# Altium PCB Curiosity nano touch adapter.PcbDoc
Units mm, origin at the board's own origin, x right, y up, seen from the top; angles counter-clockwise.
Board outline 60 x 100 mm, 2 copper layers (Top Layer, Bottom Layer); 22 components, 57 nets, 293 pads, 14 vias.
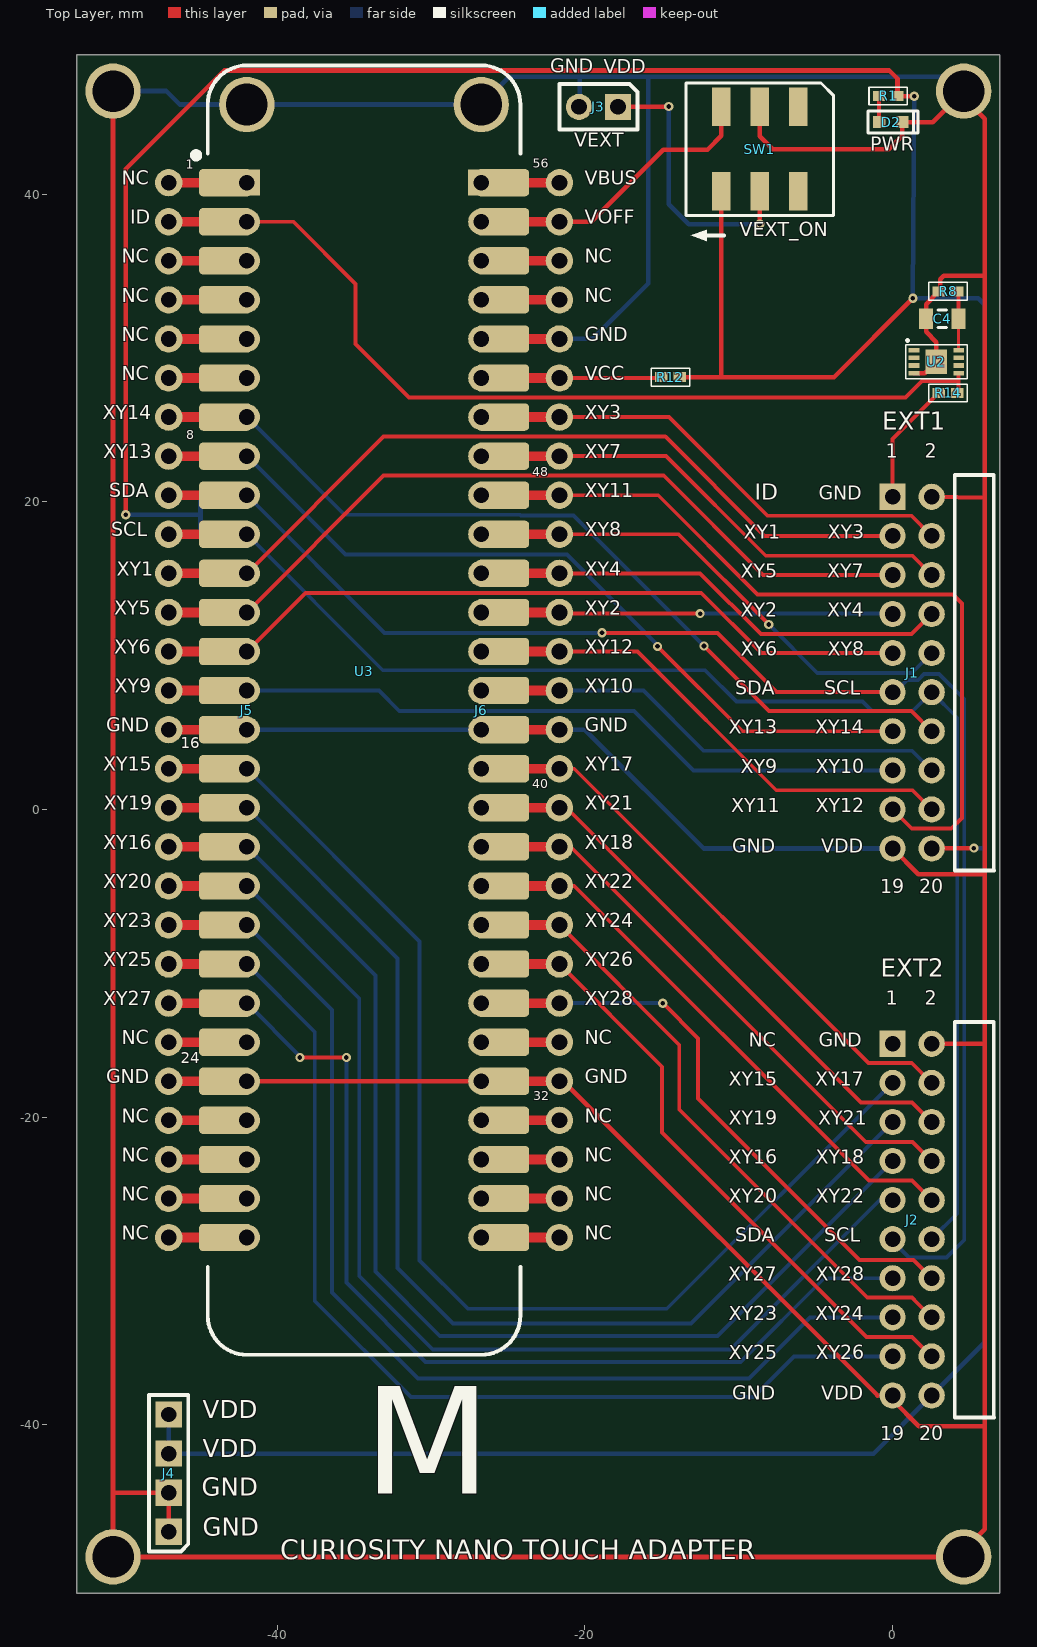
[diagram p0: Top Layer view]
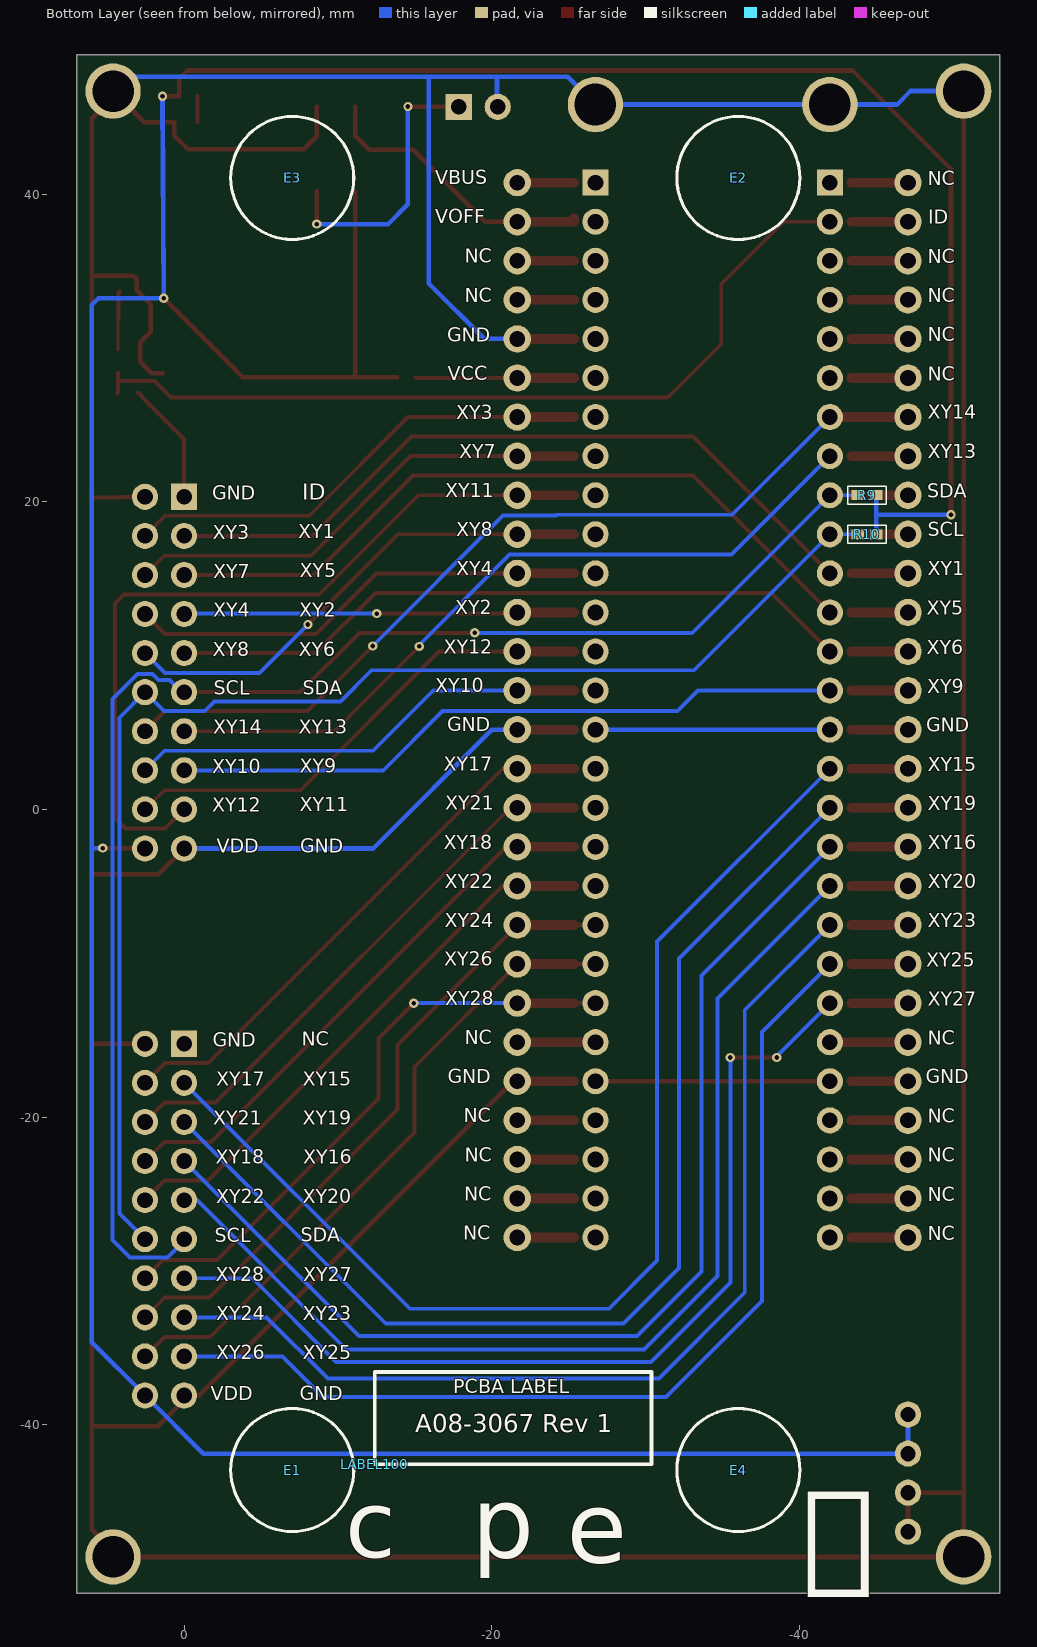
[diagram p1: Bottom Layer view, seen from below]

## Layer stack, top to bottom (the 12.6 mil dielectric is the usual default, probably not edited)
Top Solder: solder mask 0.0102, Solder Resist, Dk 3.5
Top Layer: signal copper 0.0356
Dielectric 1: dielectric 0.32, FR-4, Dk 4.8
Bottom Layer: signal copper 0.0356
Bottom Solder: solder mask 0.0102, Solder Resist, Dk 3.5

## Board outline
-53.03,-50.95 6.97,-50.95 6.97,49.05 -53.03,49.05

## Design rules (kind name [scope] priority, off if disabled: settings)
Clearance [All] p1: gap=0.2 ignorepadtopadclearanceinfootprint=FALSE except(0: Arc-Hole Track-Hole SMDPad-Hole THPad-Hole Via-Hole Fill-Hole Poly-Hole Region-Hole Text-Hole)
HoleSize [All] p1: absolutevalues=TRUE maxlimit=10 minlimit=0.025 maxpercent=80.000 minpercent=20.000
MinimumSolderMaskSliver [All] p1: minsoldermaskwidth=0.1
PolygonConnect [All] p1: connectstyle=Relief reliefconductorwidth=0.254 reliefentries=4 polygonreliefangle="90 Angle" airgapwidth=0.254
RoutingVias [All] p1: holewidth=0.3 width=0.6 viastyle="Through Hole" minholewidth=0.3 minwidth=0.6 maxholewidth=0.3 maxwidth=0.6
SilkToSilkClearance [All] p1: silktosilkclearance=0.1
SilkToSolderMaskClearance [IsPad] p1: minsilkscreentomaskgap=0.1 clearancetoexposedcopper=TRUE
SolderMaskExpansion [All] p1: expansion=0.102
Width [All] p1: maxlimit=10 minlimit=0.2 preferedwidth=0.2
26 further rules are at their usual default settings.

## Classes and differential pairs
component class "Curiosity nano touch adapter_TopLevel": E1 E2 E3 E4 LABEL100 PCB1 PCBADOC1 PCBADOC2 TEST1
component class "Curiosity nano touch adapter": C4 D2 J1 J2 J3 J4 J5 J6 R1 R8 R9 R10 R12 R14 SW1 U2 U3

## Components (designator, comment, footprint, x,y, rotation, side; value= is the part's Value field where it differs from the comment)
C4 "Generic part, no manufacturer specified." AP1-00069 3.226,31.902 r180 top value=4.7uF
D2 "Farnell no. 1652078" AP4-00017 -0.122,44.681 r180 top value=SML-310MTT86N
E1 "RUBBER FEET" AP8-00192 -7.03,-42.95 r180 bottom value=SJ-5076
E2 "RUBBER FEET" AP8-00192 -36.03,41.05 r180 bottom value=SJ-5076
E3 "RUBBER FEET" AP8-00192 -7.03,41.05 r180 bottom value=SJ-5076
E4 "RUBBER FEET" AP8-00192 -36.03,-42.95 r180 bottom value=SJ-5076
J1 "" AP8-01078 1.27,8.89 r270 top value=1125-1210S0R138R1
J2 "" AP8-01078 1.27,-26.67 r270 top value=1125-1210S0R138R1
J3 "HEADER 1x2" AP8-01074 -19.121,45.672 r180 top value=1125-1102S0S113R1
J4 "None" AP8-00176 -47.061,-43.152 r90 top value=HMTSW-104-23-F-S-237
J5 "Not suitable for pick-and-place (missing tab)" AP8-01174#1 -41.981,6.454 r270 top value=2185-128SS0CUNT1
J6 "Not suitable for pick-and-place (missing tab)" AP8-01174#2 -26.741,6.454 r270 top value=2185-128SS0CUNT1
LABEL100 "" AP8-00317 -12.395,-42.57 r180 bottom value="Label PCBA"
R1 "" AP2-00000 -0.284,46.383 r180 top value=470R
R8 "" AP2-00000 3.607,33.68 r180 top value=100k
R9 "" AP2-00000 -44.394,20.424 r0 bottom value=10k
R10 "" AP2-00000 -44.394,17.884 r0 bottom value=10k
R12 "" AP2-00000 -14.447,28.095 r0 top value=0R
R14 "" AP2-00000 3.607,27.076 r180 top value=0R
SW1 "" AP8-00684 -8.631,42.922 r180 top value=JS202011SCQN
U2 "" AP6-00409 2.845,29.108 r0 top value="ATSHA204A SWI UDFN8"
U3 "" AP8-01154 -34.361,6.454 r0 top value=CNANO56_HOST_CONN

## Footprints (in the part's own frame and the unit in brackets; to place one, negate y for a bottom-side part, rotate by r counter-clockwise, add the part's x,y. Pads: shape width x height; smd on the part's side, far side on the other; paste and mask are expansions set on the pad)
AP1-00069 [mm] "0805 Cap"
  rect 0.9x1.35 smd: 1(-1.05,0) 2(1.05,0)
  silkscreen extent -0.28,-0.57 0.28,0.57, body extent -1,-0.63 1,0.63, height 0.78
AP2-00000 [mm] "Standard 0402 SMD resistor footprint"
  rect 0.8x0.65 smd: 1(-0.6,0) 2(0.6,0)
  silkscreen extent -1.25,-0.58 1.25,0.58, body extent -0.5,-0.3 0.5,0.3, height 0.2
AP4-00017 [mm]
  rect 0.8x0.8 smd: 1(-0.75,0) 2(0.75,0)
  silkscreen extent -1.76,-0.72 1.47,0.72, body extent -0.83,-0.36 0.81,0.37, height 0.68
AP6-00409 [mm]
  rect 0.7x0.3 smd mask-1: 1(-1.45,0.75) 2(-1.45,0.25) 3(-1.45,-0.25) 4(-1.45,-0.75) 5(1.45,-0.75) 6(1.45,-0.25) 7(1.45,0.25) 8(1.45,0.75)
  rect 1.4x1.6 smd paste-0.025 mask+0.075: 9(0,0)
  silkscreen extent -2,-1.1 2,1.45, body extent -1.55,-1.05 1.55,1.05, height 0.6
AP8-00176 [mm]
  rect 1.7x1.7 / inner round 1.7 / far side round 1.7 hole 1: 1(-3.81,0) 2(-1.27,0) 3(1.27,0) 4(3.81,0)
  silkscreen extent -5.08,-1.27 5.08,1.27, body extent -5.08,-1.24 5.08,1.24, height 8.56
AP8-00192 [mm]
  silkscreen extent -4,-4 4,4, body extent -4,-4 4,4, height 2.79
AP8-00317 [mm] "Placement area for 18x6mm sticker"
  silkscreen extent 0,0 18,6
AP8-00684 [mm] "Slide Switch, C&K, 2 Pos 2 Pol"
  rect 1.2x2.5 smd: 1(-2.5,-2.75) 2(0,-2.75) 3(2.5,-2.75) 4(-2.5,2.75) 5(0,2.75) 6(2.5,2.75)
  silkscreen extent -4.8,-4.3 4.8,4.3, body extent -4.52,-3.8 4.55,3.8, height 5.5
AP8-01074 [mm] "Pin header 1 x 2,  2.54mm, THM, PIP, with Pick plate"
  rect 2.1x2.1 on Top Paste: 0(-1.27,0) 0(1.27,0)
  rect 1.7x1.7 / inner round 1.7 / far side rect 1.7x1.7 hole 1.02: 1(-1.27,0)
  round 1.7 hole 1.02: 2(1.27,0)
  silkscreen extent -2.54,-1.48 2.54,1.48, body extent -2.54,-1.27 2.54,1.27, height 8.38
AP8-01078 [mm] "2x10 Right angle 2.54mm THM, Pick plate"
  rect 1.7x1.7 / inner round 1.7 / far side rect 1.7x1.7 hole 1.02: 1(-11.43,-1.27)
  rect 2.1x2.1 on Top Paste: 1(-11.43,-1.27) 2(-11.43,1.27) 3(-8.89,-1.27) 4(-8.89,1.27) 5(-6.35,-1.27) 6(-6.35,1.27) 7(-3.81,-1.27) 8(-3.81,1.27) 9(-1.27,-1.27) 10(-1.27,1.27) 11(1.27,-1.27) 12(1.27,1.27) 13(3.81,-1.27) 14(3.81,1.27) 15(6.35,-1.27) 16(6.35,1.27) 17(8.89,-1.27) 18(8.89,1.27) 19(11.43,-1.27) 20(11.43,1.27)
  round 1.7 hole 1.02: 2(-11.43,1.27) 3(-8.89,-1.27) 4(-8.89,1.27) 5(-6.35,-1.27) 6(-6.35,1.27) 7(-3.81,-1.27) 8(-3.81,1.27) 9(-1.27,-1.27) 10(-1.27,1.27) 11(1.27,-1.27) 12(1.27,1.27) 13(3.81,-1.27) 14(3.81,1.27) 15(6.35,-1.27) 16(6.35,1.27) 17(8.89,-1.27) 18(8.89,1.27) 19(11.43,-1.27) 20(11.43,1.27)
  silkscreen extent -12.85,2.77 12.85,5.31, body extent -12.7,-1.59 12.7,11.29, height 5
AP8-01154 [mil] "Host Footprint with Curiosity Nano Bd Surface-Mounted"
  round 70 hole 40.16 paste-750: 1(-500,1350) 2(-500,1250) 3(-500,1150) 4(-500,1050) 5(-500,950) 6(-500,850) 7(-500,750) 8(-500,650) 9(-500,550) 10(-500,450) 11(-500,350) 12(-500,250) 13(-500,150) 14(-500,50) 15(-500,-50) 16(-500,-150) 17(-500,-250) 18(-500,-350) 19(-500,-450) 20(-500,-550) 21(-500,-650) 22(-500,-750) 23(-500,-850) 24(-500,-950) 25(-500,-1050) 26(-500,-1150) 27(-500,-1250) 28(-500,-1350) 29(500,-1350) 30(500,-1250) 31(500,-1150) 32(500,-1050) 33(500,-950) 34(500,-850) 35(500,-750) 36(500,-650) 37(500,-550) 38(500,-450) 39(500,-350) 40(500,-250) 41(500,-150) 42(500,-50) 43(500,50) 44(500,150) 45(500,250) 46(500,350) 47(500,450) 48(500,550) 49(500,650) 50(500,750) 51(500,850) 52(500,950) 53(500,1050) 54(500,1150) 55(500,1250) 56(500,1350)
  rrect30% 135x70 smd paste-70: 1(-355,1350) 2(-355,1250) 3(-355,1150) 4(-355,1050) 5(-355,950) 6(-355,850) 7(-355,750) 8(-355,650) 9(-355,550) 10(-355,450) 11(-355,350) 12(-355,250) 13(-355,150) 14(-355,50) 15(-355,-50) 16(-355,-150) 17(-355,-250) 18(-355,-350) 19(-355,-450) 20(-355,-550) 21(-355,-650) 22(-355,-750) 23(-355,-850) 24(-355,-950) 25(-355,-1050) 26(-355,-1150) 27(-355,-1250) 28(-355,-1350) 29(355,-1350) 30(355,-1250) 31(355,-1150) 32(355,-1050) 33(355,-950) 34(355,-850) 35(355,-750) 36(355,-650) 37(355,-550) 38(355,-450) 39(355,-350) 40(355,-250) 41(355,-150) 42(355,-50) 43(355,50) 44(355,150) 45(355,250) 46(355,350) 47(355,450) 48(355,550) 49(355,650) 50(355,750) 51(355,850) 52(355,950) 53(355,1050) 54(355,1150) 55(355,1250) 56(355,1350)
  round 141.73 hole 106.3: 52(-300,1550) 52(300,1550)
  Top Layer lines w25: -500,-1350 -355,-1350 ; -500,-1250 -355,-1250 ; -500,-1150 -355,-1150 ; -500,-1050 -355,-1050 ; -500,-950 -355,-950 ; -500,-450 -355,-450 ; -500,-350 -355,-350 ; -500,-250 -355,-250 ; -500,-150 -355,-150 ; -500,-50 -355,-50 ; -500,50 -355,50 ; -500,150 -355,150 ; -500,250 -355,250 ; -500,350 -355,350 ; -500,450 -355,450 ; -500,550 -355,550 ; -500,650 -355,650 ; -500,850 -355,850 ; -500,950 -355,950 ; -500,1050 -355,1050 ; -500,1150 -355,1150 ; -500,1250 -355,1250 ; -500,1350 -355,1350 ; 355,-1350 500,-1350 ; 355,-1250 500,-1250 ; 355,-1150 500,-1150 ; 355,-1050 500,-1050 ; 355,-950 500,-950 ; 355,-450 500,-450 ; 355,-250 500,-250 ; 355,-150 500,-150 ; 355,-50 500,-50 ; 355,50 500,50 ; 355,150 500,150 ; 355,250 500,250 ; 355,350 500,350 ; 355,450 500,450 ; 355,550 500,550 ; 355,650 500,650 ; 355,750 500,750 ; 355,850 500,850 ; 355,950 500,950 ; 355,1050 500,1050 ; 355,1150 500,1150 ; 355,1250 500,1250 ; 355,1350 500,1350
  silkscreen extent -438,-1650 400,1650
AP8-01174#1 [mm] "THM Pin-socket 1x28 100mil pitch"
  rect 1.7x1.7 / inner round 1.7 / far side rect 1.7x1.7 hole 1.02: 1(-34.29,0)
  round 1.7 hole 1.02: 2(-31.75,0) 3(-29.21,0) 4(-26.67,0) 5(-24.13,0) 6(-21.59,0) 7(-19.05,0) 8(-16.51,0) 9(-13.97,0) 10(-11.43,0) 11(-8.89,0) 12(-6.35,0) 13(-3.81,0) 14(-1.27,0) 15(1.27,0) 16(3.81,0) 17(6.35,0) 18(8.89,0) 19(11.43,0) 20(13.97,0) 21(16.51,0) 22(19.05,0) 23(21.59,0) 24(24.13,0) 25(26.67,0) 26(29.21,0) 27(31.75,0) 28(34.29,0)
  body extent -35.81,-1.21 35.81,1.21, height 8.51
AP8-01174#2 [mm] "THM Pin-socket 1x28 100mil pitch"
  rect 1.7x1.7 hole 1.02: 1(-34.29,0)
  round 1.7 hole 1.02: 2(-31.75,0) 3(-29.21,0) 4(-26.67,0) 5(-24.13,0) 6(-21.59,0) 7(-19.05,0) 8(-16.51,0) 9(-13.97,0) 10(-11.43,0) 11(-8.89,0) 12(-6.35,0) 13(-3.81,0) 14(-1.27,0) 15(1.27,0) 16(3.81,0) 17(6.35,0) 18(8.89,0) 19(11.43,0) 20(13.97,0) 21(16.51,0) 22(19.05,0) 23(21.59,0) 24(24.13,0) 25(26.67,0) 26(29.21,0) 27(31.75,0) 28(34.29,0)
  body extent -35.81,-1.21 35.81,1.21, height 8.51

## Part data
C4: library part A01-0486, "Ceramic capacitor, SMD 0805, X7R, 16V, 10%,", Manufacturer="YAGEO CORP", MPN=CC0805KKX7R7BB475, TemperatureRange="-55 to +125 deg C", Tolerance=10%
D2: library part A10-0056, "LED, Green, 570nm, SMD 0603", Color=GRN, Manufacturer=ROHM, MPN=SML-310MTT86N, TemperatureRange=-30
E1 E2 E3 E4: library part A08-0053, "2.8mm adhesive feet,diam 8.0mm", Manufacturer=3M, MPN=SJ-5076
J1 J2: library part A08-2786, "Pin header, 2x10, Right Angle, 2.54mm, THM, Pin In Paste", Manufacturer="WCON HARDWARE ELECTRONICS CO., LTD", MPN=1125-1210S0R138R1
J3: library part A08-2782, "1x2 pin header, 2.54mm pitch, Pin-in-Paste THM", Manufacturer="WCON HARDWARE ELECTRONICS CO., LTD", MPN=1125-1102S0S113R1, TemperatureRange="-40°C to +105°C"
J4: library part A08-1653, "1x4 pin header, 2.54mm pitch, Pin-in-Paste THM", TemperatureRange="- 55 ï¿½C to + 125 ï¿½C"
J5 J6: library part A08-2989, "1x28 receptacle pin socket, 2.54mm pitch THM, BULK packaging", Manufacturer=WCON, MPN=2185-128SS0CUNT1, TemperatureRange="-40°C to +105°C"
LABEL100: library part A09-0611, "PCBA identification label PP Top White Gloss", Manufacturer="ACT Logimark AS", MPN=505462
R1: library part A02-0204, "Thick film resistor, SMD 0402, 1/16W, 1%", Manufacturer=ASJ, MPN=CR10-4700-FK, TemperatureRange="-55 - +125 deg C", Tolerance="1 %"
R8: library part A02-0260, "Thick film resistor, SMD 0402, 1/16W, 1%", Manufacturer=ASJ, MPN=CR10-1003-FK, TemperatureRange="-55� to +125�C", Tolerance="1 %"
R9 R10: library part A02-0236, "Thick film resistor, SMD 0402, 1/16W, 1%", Manufacturer=vishay, MPN=CRCW040210K0FKED, TemperatureRange="-55 - +125 deg C", Tolerance="1 %"
R12 R14: library part A02-0163, "RES 0.0 OHM 1/16W 0402 SMD", Manufacturer=(n/a), MPN=RMCF0402ZT0R00, TemperatureRange="-55 - +125 deg C", Tolerance="1 %"
SW1: library part A08-1643, "Slide Switch, C&K, 2 Pos 2 Pol, SMD", Manufacturer="C&K Components", MPN=JS202011SCQN
U2: library part A06-1276, "ATSHA204A with 1-wire interface and UDFN8 package", Manufacturer=ATMEL, MPN=ATSHA204A-MAHCZ-T
U3: library part A08-2940, "56-pin Header HOST (for CNANO solder mounting)"

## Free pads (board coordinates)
  round 3.6 hole 2.7 paste-2.6: 666(-50.68,-48.6) 666(-50.68,46.7) 666(4.62,-48.6) 666(4.62,46.7)

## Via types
v1: diameter 0.6, hole 0.3, Top Layer to Bottom Layer, tented both sides, 14 vias

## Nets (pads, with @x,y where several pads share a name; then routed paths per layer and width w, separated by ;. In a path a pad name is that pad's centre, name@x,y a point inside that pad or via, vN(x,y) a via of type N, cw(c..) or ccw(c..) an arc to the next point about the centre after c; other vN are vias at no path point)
"EXT1 XY1": J1.3@0,17.78 J5.11 U3.11 | length 48.3
  Top Layer w0.254: J5.11 -33.091,24.234 -14.778,24.234 -8.324,17.78 J1.3@0,17.78
"EXT1 XY2": J1.7@0,12.7 J6.12 U3.45 | length 21.8
  Top Layer w0.254: U3.45@-21.661,12.804 -21.585,12.728 v1(-12.517,12.728)
  Bottom Layer w0.254: v1(-12.517,12.728) -0.18,12.728 -0.104,12.804 J1.7@0,12.7
"EXT1 XY3": J1.4@2.54,17.78 J6.7 U3.50 | length 27.4
  Top Layer w0.254: U3.50@-21.661,25.504 -14.549,25.504 -8.134,19.089 1.231,19.089 J1.4@2.54,17.78
"EXT1 XY4": J1.8@2.54,12.7 J6.11 U3.46 | length 26.4
  Top Layer w0.254: U3.46@-21.661,15.344 -12.517,15.344 -8.563,11.39 1.23,11.39 J1.8@2.54,12.7
"EXT1 XY5": J1.5@0,15.24 J5.12 U3.12 | length 48.3
  Top Layer w0.254: J5.12 -33.091,21.694 -14.879,21.694 -8.425,15.24 J1.5@0,15.24
"EXT1 XY6": J1.9@0,10.16 J5.13 U3.13 | length 45.2
  Top Layer w0.254: J5.13 -38.171,14.074 -12.441,14.074 -8.527,10.16 J1.9@0,10.16
"EXT1 XY7": J1.6@2.54,15.24 J6.8 U3.49 | length 27.4
  Top Layer w0.254: U3.49@-21.661,22.964 -14.727,22.964 -8.25,16.487 1.293,16.487 J1.6@2.54,15.24
"EXT1 XY8": J1.10@2.54,10.16 J6.10 U3.47 | length 28.5
  Top Layer w0.254: U3.47@-21.661,17.884 -13.914,17.884 v1(-8.047,12.017)
  Bottom Layer w0.254: v1(-8.047,12.017) -4.897,8.867 1.247,8.867 J1.10@2.54,10.16
"EXT1 XY9": J1.15@0,2.54 J5.14 U3.14 | length 44.1
  Bottom Layer w0.254: J5.14 -33.396,7.724 -32.072,6.4 -16.806,6.4 -12.946,2.54 J1.15@0,2.54
"EXT1 XY10": J1.16@2.54,2.54 J6.14 U3.43 | length 26.3
  Bottom Layer w0.254: U3.43@-21.661,7.724 -16.2,7.724 -12.288,3.812 1.268,3.812 J1.16@2.54,2.54
"EXT1 XY11": J1.17@0,0 J6.9 U3.48 | length 48.3
  Top Layer w0.254: U3.48@-21.661,20.424 -15.235,20.424 -8.783,13.972 3.917,13.972 4.501,13.388 4.501,-0.556 3.815,-1.242 1.242,-1.242 J1.17@0,0
"EXT1 XY12": J1.18@2.54,0 J6.13 U3.44 | length 28.5
  Top Layer w0.254: U3.44@-21.661,10.264 -16.581,10.264 -7.564,1.247 1.293,1.247 J1.18@2.54,0
"EXT1 XY13": J1.13@0,5.08 J5.8 U3.8 | length 49.4
  Top Layer w0.254: v1(-15.286,10.594) -9.771,5.08 J1.13@0,5.08
  Bottom Layer w0.254: J5.8 -35.577,16.56 -21.157,16.56 -15.286,10.688 v1(-15.286,10.594)
"EXT1 XY14": J1.14@2.54,5.08 J5.7 U3.7 | length 58.1
  Top Layer w0.254: v1(-12.263,10.62) -8.032,6.389 1.231,6.389 J1.14@2.54,5.08
  Top Layer w0.635: U3.7@-47.061,25.504 J5.7
  Bottom Layer w0.254: J5.7 -35.631,19.154 -24.226,19.154 -24.172,19.1 -20.743,19.1 v1(-12.263,10.62)
"EXT2 XY15": J2.3@0,-17.78 J5.16 U3.16 | length 74.7
  Bottom Layer w0.254: J5.16 -30.754,-8.583 -30.754,-29.317 -27.61,-32.461 -14.681,-32.461 J2.3@0,-17.78
"EXT2 XY16": J2.7@0,-22.86 J5.18 U3.18 | length 71.2
  Bottom Layer w0.254: J5.18 -33.624,-10.793 -33.624,-30.053 -29.439,-34.239 -11.379,-34.239 J2.7@0,-22.86
"EXT2 XY17": J2.4@2.54,-17.78 J6.16 U3.41 | length 33.1
  Top Layer w0.254: U3.41@-21.661,2.644 -20.696,2.644 -1.57,-16.482 1.242,-16.482 J2.4@2.54,-17.78
  Bottom Layer w0.254: U3.41@-21.661,2.644 U3.41@-21.178,2.644
"EXT2 XY18": J2.8@2.54,-22.86 J6.18 U3.39 | length 37
  Top Layer w0.254: U3.39@-21.661,-2.436 -20.924,-2.436 -1.747,-21.613 1.293,-21.613 J2.8@2.54,-22.86
  Top Layer w0.635: U3.39@-25.344,-2.436 U3.39@-21.661,-2.436
  Bottom Layer w0.254: U3.39@-21.661,-2.436 U3.39@-21.001,-2.436
"EXT2 XY19": J2.5@0,-20.32 J5.17 U3.17 | length 73.1
  Bottom Layer w0.254: J5.17 -32.177,-9.7 -32.177,-29.825 -28.575,-33.426 -13.106,-33.426 J2.5@0,-20.32
"EXT2 XY20": J2.9@0,-25.4 J5.19 U3.19 | length 69
  Bottom Layer w0.254: J5.19 -34.671,-12.286 -34.671,-30.328 -29.896,-35.103 -10.541,-35.103 -0.838,-25.4 J2.9@0,-25.4
"EXT2 XY21": J2.6@2.54,-20.32 J6.17 U3.40 | length 33.2
  Top Layer w0.254: U3.40@-21.661,0.104 -21.204,0.104 -2.052,-19.048 1.268,-19.048 J2.6@2.54,-20.32
  Bottom Layer w0.254: U3.40@-21.661,0.104 U3.40@-21.153,0.104
"EXT2 XY22": J2.10@2.54,-25.4 J6.19 U3.38 | length 32.7
  Top Layer w0.254: U3.38@-21.661,-4.976 -20.696,-4.976 -1.544,-24.128 1.268,-24.128 J2.10@2.54,-25.4
"EXT2 XY23": J2.15@0,-33.02 J5.20 U3.20 | length 70.3
  Top Layer w0.635: U3.20@-47.061,-7.516 U3.20@-43.378,-7.516
  Bottom Layer w0.254: J5.20 -36.449,-13.048 -36.449,-31.42 -30.861,-37.008 -9.347,-37.008 -5.359,-33.02 J2.15@0,-33.02
"EXT2 XY24": J2.16@2.54,-33.02 J6.20 U3.37 | length 42.3
  Top Layer w0.254: J6.20 U3.37@-25.344,-7.516 ; U3.37@-21.661,-7.516 -13.868,-15.309 -13.868,-19.507 -1.651,-31.725 1.248,-31.725 1.397,-31.873 1.397,-31.877 J2.16@2.54,-33.02
  Top Layer w0.635: U3.37@-25.344,-7.516 U3.37@-21.661,-7.516
"EXT2 XY25": J2.17@0,-35.56 J5.21 U3.21 | length 68.7
  Top Layer w0.635: U3.21@-47.061,-10.056 U3.21@-43.378,-10.056
  Bottom Layer w0.254: J5.21 -37.567,-14.47 -37.567,-31.953 -31.318,-38.202 -9.042,-38.202 -6.401,-35.56 J2.17@0,-35.56
"EXT2 XY26": J2.18@2.54,-35.56 J6.21 U3.36 | length 42.3
  Top Layer w0.254: J6.21 U3.36@-25.344,-10.056 ; U3.36@-21.661,-10.056 -14.986,-16.731 -14.986,-21.006 -1.702,-34.29 1.27,-34.29 J2.18@2.54,-35.56
  Top Layer w0.635: U3.36@-25.344,-10.056 U3.36@-21.661,-10.056
"EXT2 XY27": J2.13@0,-30.48 J5.22 U3.22 | length 66.2
  Top Layer w0.254: v1(-38.532,-16.129) v1(-35.509,-16.129)
  Top Layer w0.635: U3.22@-47.061,-12.596 U3.22@-43.378,-12.596
  Bottom Layer w0.254: J5.22 v1@-38.49,-16.087 ; v1(-35.509,-16.129) -35.509,-30.766 -30.36,-35.916 -9.881,-35.916 -4.445,-30.48 J2.13@0,-30.48
"EXT2 XY28": J2.14@2.54,-30.48 J6.22 U3.35 | length 39
  Top Layer w0.254: J6.22 U3.35@-25.344,-12.596 ; v1(-14.936,-12.597) -12.649,-14.884 -12.649,-18.796 -2.142,-29.303 1.363,-29.303 J2.14@2.54,-30.48
  Top Layer w0.635: U3.35@-25.344,-12.596 U3.35@-21.661,-12.596
  Bottom Layer w0.254: U3.35@-21.661,-12.596 -21.66,-12.597 v1(-14.936,-12.597)
GND: C4.2 D2.1 J1.2@2.54,20.32 J1.19@0,-2.54 J2.2@2.54,-15.24 J2.19@0,-38.1 J3.2 J4.1 J4.2 J5.15 J5.24 J6.5 J6.15 J6.24 pad.666 R8.2 SW1.2 U2.4 U2.9 U3.15 U3.24 U3.33 U3.42 U3.52 | length 466.1
  Top Layer w0.3: pad.666@-50.68,46.7 -50.68,-44.473 ; J4.1 J4.2 -50.629,-44.422 -50.68,-44.473 ; J5.24 J6.24 ; U3.52@-41.981,45.824 U3.52@-41.854,45.951 ; U3.33@-21.661,-17.676 -21.407,-17.676 -0.983,-38.1 ; SW1.2 -8.631,43.767 -7.786,42.922 -0.256,42.922 0.628,43.805 D2.1 2.601,44.681 4.62,46.7 4.62,46.267 5.994,44.892 5.994,34.696 ; J2.19@0,-38.397 1.707,-40.104 5.994,-40.104 ; J1.19@0,-2.54 1.674,-4.214 5.944,-4.214 ; U2.4 2.095,28.358 U2.9 2.845,30.378 2.176,31.047 C4.2 2.176,32.849 R8.2 3.086,33.76 3.086,34.455 3.327,34.696 5.994,34.696 ; J2.2@2.54,-15.24 5.994,-15.24 ; J1.2@2.54,20.32 5.944,20.27 ; -50.68,-44.473 -50.68,-48.6 4.62,-48.6 4.62,-48.167 5.994,-46.792 5.994,-40.104 ; 5.994,-40.104 5.994,-15.24 ; 5.994,-15.24 5.994,34.696
  Bottom Layer w0.3: pad.666@-50.68,46.7 -47.226,46.7 -46.35,45.824 -41.981,45.824 -26.741,45.824 -24.933,47.632 -20.34,47.632 ; J5.15 J6.15 ; U3.42@-21.661,5.184 -20.01,5.184 -12.286,-2.54 0,-2.54 J1.19@0,-2.761 ; U3.52@-21.661,30.584 -19.502,30.584 -15.895,34.191 -15.895,47.602 ; J3.2 -20.34,45.722 -20.34,47.632 ; pad.666@4.62,46.7 3.688,47.632 -20.34,47.632
"I2C SCL": J1.12@2.54,7.62 J2.12@2.54,-27.94 J5.10 R10.2 U3.10 | length 88.5
  Bottom Layer w0.254: R10.2 J5.10 -33.145,9.048 -12.19,9.048 -10.155,7.013 -1.965,7.013 -1.341,6.389 1.309,6.389 2.54,7.62 4.202,5.958 4.202,-26.278 J2.12@2.54,-27.94
"I2C SDA": J1.11@0,7.62 J2.11@0,-27.94 J5.9 R9.2 U3.9 | length 95.8
  Top Layer w0.254: v1(-18.889,11.48) -11.396,11.48 -7.536,7.62 J1.11@0,7.62
  Bottom Layer w0.254: R9.2 J5.9 -33.037,11.48 v1(-18.889,11.48) ; J2.11@0,-27.94 0,-28.067 1.067,-29.134 3.505,-29.134 4.656,-27.983 4.656,7.168 3.028,8.797 2.052,8.797 1.668,8.413 0.948,8.413 0.155,7.62 J1.11@0,7.62
ID: J5.2 R14.1 U2.5 U3.2 | length 55
  Top Layer w0.254: J5.2 -38.958,38.204 -34.92,34.165 -34.92,30.254 -31.44,26.774 0.849,26.774 1.914,27.838 4.242,27.838 ; U2.5 4.295,27.115 R14.1@4.334,27.076
ID_XPRO_EXT1: J1.1@0,20.32 R14.2 | length 8
  Top Layer w0.254: J1.1@0,20.32 0,24.07 2.734,26.803 2.734,26.878 2.932,27.076 R14.2
NetC4_1: C4.1 R8.1 U2.8 | length 3.9
  Top Layer w0.2: C4.1 4.295,31.883 U2.8
  Top Layer w0.254: R8.1 4.276,33.611 C4.1
NetD2_2: D2.2 R1.2 | length 1.7
  Top Layer w0.254: R1.2 -0.884,44.693 D2.2
NetJ5_1: J5.1 U3.1
NetJ5_3: J5.3 U3.3
NetJ5_4: J5.4 U3.4
NetJ5_5: J5.5 U3.5
NetJ5_6: J5.6 U3.6
NetJ5_23: J5.23 U3.23 | length 5.1
  Top Layer w0.635: U3.23@-47.061,-15.136 -43.378,-15.136 J5.23
NetJ5_25: J5.25 U3.25
NetJ5_26: J5.26 U3.26
NetJ5_27: J5.27 U3.27
NetJ5_28: J5.28 U3.28
NetJ6_3: J6.3 U3.54
NetJ6_4: J6.4 U3.53
NetJ6_23: J6.23 U3.34 | length 5.1
  Top Layer w0.635: J6.23 U3.34@-21.661,-15.136
NetJ6_25: J6.25 U3.32
NetJ6_26: J6.26 U3.31
NetJ6_27: J6.27 U3.30
NetJ6_28: J6.28 U3.29
VBUS: J6.1 U3.56
VCC: J6.6 R12.1 U3.51 | length 6.6
  Top Layer w0.254: U3.51@-21.661,28.044 -15.098,28.044 R12.1
VEXT: J3.1 SW1.5 | length 18.2
  Top Layer w0.3: J3.1 -14.574,45.672 v1(-14.549,45.697) ; v1(-8.631,38.052) SW1.5
  Bottom Layer w0.3: v1(-14.549,45.697) -14.549,39.347 -13.254,38.052 v1(-8.631,38.052)
VOFF: J6.2 SW1.3 U3.55 | length 15
  Top Layer w0.3: U3.55@-21.661,38.204 -19.578,38.204 -14.905,42.878 -12.034,42.878 -11.131,43.781 SW1.3
  Top Layer w0.635: U3.55@-25.344,38.204 U3.55@-25.344,38.433
VTAG: J1.20@2.54,-2.54 J2.20@2.54,-38.1 J4.3 J4.4 R1.1 R9.1 R10.1 R12.2 SW1.6 | length 262.1
  Top Layer w0.3: v1(-49.855,19.154) -49.855,41.633 -43.454,48.034 -17.8,48.034 -0.223,48.034 0.316,47.494 R1.1 0.342,46.357 v1(1.402,46.357) ; R12.2 -11.196,28.095 ; SW1.6 -11.131,28.16 -11.196,28.095 ; v1(1.321,33.223) -3.808,28.095 -11.196,28.095 ; J1.20@2.54,-2.54 2.565,-2.515 v1(5.283,-2.515)
  Bottom Layer w0.3: v1(-49.855,19.154) -45.045,19.154 -44.994,19.103 ; J4.4 J4.3 -1.242,-41.882 2.54,-38.1 5.994,-34.646 5.994,-2.523 ; R10.1 -44.994,19.103 ; R9.1 -44.994,19.103 ; v1@1.326,46.281 v1(1.402,46.357) v1(1.321,33.223) 5.563,33.223 5.994,32.791 5.994,-2.523 ; v1(5.283,-2.515) 5.986,-2.515 5.994,-2.523
pads on no net: J1.1@0,20.32 J1.2@2.54,20.32 J1.3@0,17.78 J1.4@2.54,17.78 J1.5@0,15.24 J1.6@2.54,15.24 J1.7@0,12.7 J1.8@2.54,12.7 J1.9@0,10.16 J1.10@2.54,10.16 J1.11@0,7.62 J1.12@2.54,7.62 J1.13@0,5.08 J1.14@2.54,5.08 J1.15@0,2.54 J1.16@2.54,2.54 J1.17@0,0 J1.18@2.54,0 J1.19@0,-2.54 J1.20@2.54,-2.54 J2.1 J2.2@2.54,-15.24 J2.3@0,-17.78 J2.4@2.54,-17.78 J2.5@0,-20.32 J2.6@2.54,-20.32 J2.7@0,-22.86 J2.8@2.54,-22.86 J2.9@0,-25.4 J2.10@2.54,-25.4 J2.11@0,-27.94 J2.12@2.54,-27.94 J2.13@0,-30.48 J2.14@2.54,-30.48 J2.15@0,-33.02 J2.16@2.54,-33.02 J2.17@0,-35.56 J2.18@2.54,-35.56 J2.19@0,-38.1 J2.20@2.54,-38.1 J3.0 SW1.1 SW1.4 U2.1 U2.2 U2.3 U2.6 U2.7

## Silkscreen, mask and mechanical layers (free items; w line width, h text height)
Top Overlay:
  region: -13.117,37.315 -12.085,37.696 -12.085,36.934
  lines w0.254: -12.316,37.315 -10.958,37.315
  text "GND" at -22.25,47.6 h1.52
  text "VDD" at -18.771,47.574 h1.52
  text "VEXT" at -20.701,42.799 h1.52
  text "PWR" at -1.468,42.522 h1.52
  text "56" at -23.388,41.531 h1
  text "1" at -45.943,41.455 h1
  text "NC" at -50.109,40.311 h1.52
  text "VBUS" at -20.015,40.311 h1.52
  text "ID" at -49.568,37.771 h1.52
  text "VOFF" at -20.015,37.771 h1.52
  text "VEXT_ON" at -9.952,36.959 h1.52
  text "NC" at -50.109,35.231 h1.52
  text "NC" at -20.015,35.231 h1.52
  text "NC" at -50.109,32.691 h1.52
  text "NC" at -20.015,32.691 h1.52
  text "NC" at -50.109,30.151 h1.52
  text "GND" at -20.015,30.151 h1.52
  text "NC" at -50.109,27.611 h1.52
  text "VCC" at -20.015,27.611 h1.52
  text "XY14" at -51.335,25.071 h1.52
  text "XY3" at -20.015,25.071 h1.52
  text "EXT1" at -0.66,24.282 h2
  text "8" at -45.918,23.878 h1
  text "1" at -0.452,22.558 h1.52
  text "2" at 2.088,22.558 h1.52
  text "XY13" at -51.303,22.531 h1.52
  text "XY7" at -20.015,22.531 h1.52
  text "48" at -23.439,21.465 h1
  text "SDA" at -50.929,19.991 h1.52
  text "XY11" at -20.015,19.991 h1.52
  text "GND" at -4.785,19.849 h1.52
  text "ID" at -8.961,19.771 h1.78
  text "SCL" at -50.803,17.451 h1.52
  text "XY8" at -20.015,17.451 h1.52
  text "XY1" at -9.692,17.309 h1.52
  text "XY3" at -4.216,17.309 h1.52
  text "XY1" at -50.424,14.911 h1.52
  text "XY4" at -20.015,14.911 h1.52
  text "XY5" at -9.877,14.769 h1.52
  text "XY7" at -4.244,14.769 h1.52
  text "XY5" at -50.594,12.371 h1.52
  text "XY2" at -20.015,12.371 h1.52
  text "XY2" at -9.876,12.229 h1.52
  text "XY4" at -4.252,12.229 h1.52
  text "XY6" at -50.595,9.831 h1.52
  text "XY12" at -20.015,9.831 h1.52
  text "XY6" at -9.879,9.689 h1.52
  text "XY8" at -4.219,9.689 h1.52
  text "XY9" at -50.578,7.291 h1.52
  text "XY10" at -20.015,7.291 h1.52
  text "SDA" at -10.242,7.149 h1.52
  text "SCL" at -4.454,7.149 h1.52
  text "GND" at -51.107,4.751 h1.52
  text "GND" at -20.015,4.751 h1.52
  text "XY13" at -10.65,4.609 h1.52
  text "XY14" at -5.034,4.609 h1.52
  text "16" at -46.274,3.711 h1.2
  text "XY15" at -51.312,2.211 h1.52
  text "XY17" at -20.015,2.211 h1.52
  text "XY9" at -9.86,2.069 h1.52
  text "XY10" at -4.996,2.069 h1.52
  text "40" at -23.439,1.171 h1
  text "XY19" at -51.296,-0.329 h1.52
  text "XY21" at -20.015,-0.329 h1.52
  text "XY11" at -10.474,-0.471 h1.52
  text "XY12" at -5.008,-0.471 h1.52
  text "XY16" at -51.313,-2.869 h1.52
  text "XY18" at -20.015,-2.869 h1.52
  text "GND" at -10.436,-3.122 h1.52
  text "VDD" at -4.648,-3.122 h1.52
  text "XY20" at -51.301,-5.409 h1.52
  text "XY22" at -20.015,-5.409 h1.52
  text "19" at -0.808,-5.738 h1.52
  text "20" at 1.732,-5.738 h1.52
  text "XY23" at -51.303,-7.949 h1.52
  text "XY24" at -20.015,-7.949 h1.52
  text "XY25" at -51.312,-10.489 h1.52
  text "XY26" at -20.015,-10.489 h1.52
  text "EXT2" at -0.78,-11.278 h2
  text "1" at -0.452,-13.002 h1.52
  text "2" at 2.088,-13.002 h1.52
  text "XY27" at -51.329,-13.029 h1.52
  text "XY28" at -20.015,-13.029 h1.52
  text "NC" at -50.109,-15.569 h1.52
  text "NC" at -20.015,-15.569 h1.52
  text "NC" at -9.349,-15.711 h1.52
  text "GND" at -4.785,-15.711 h1.52
  text "24" at -46.274,-16.762 h1.2
  text "GND" at -51.107,-18.109 h1.52
  text "GND" at -20.015,-18.109 h1.52
  text "XY15" at -10.66,-18.251 h1.52
  text "XY17" at -5.027,-18.251 h1.52
  text "32" at -23.363,-19.098 h1
  text "NC" at -50.109,-20.649 h1.52
  text "NC" at -20.015,-20.649 h1.52
  text "XY19" at -10.642,-20.791 h1.52
  text "XY21" at -4.823,-20.791 h1.52
  text "NC" at -50.109,-23.189 h1.52
  text "NC" at -20.015,-23.189 h1.52
  text "XY16" at -10.661,-23.331 h1.52
  text "XY18" at -5.001,-23.331 h1.52
  text "NC" at -50.109,-25.729 h1.52
  text "NC" at -20.015,-25.729 h1.52
  text "XY20" at -10.647,-25.871 h1.52
  text "XY22" at -5.008,-25.871 h1.52
  text "NC" at -50.109,-28.269 h1.52
  text "NC" at -20.015,-28.269 h1.52
  text "SDA" at -10.242,-28.411 h1.52
  text "SCL" at -4.454,-28.411 h1.52
  text "XY27" at -10.678,-30.951 h1.52
  text "XY28" at -5.001,-30.951 h1.52
  text "XY23" at -10.65,-33.491 h1.52
  text "XY24" at -5.034,-33.491 h1.52
  text "XY25" at -10.66,-36.031 h1.52
  text "XY26" at -5.01,-36.031 h1.52
  text "GND" at -10.436,-38.682 h1.52
  text "VDD" at -4.648,-38.682 h1.52
  text "VDD" at -44.851,-39.977 h2
  text "19" at -0.808,-41.298 h1.52
  text "20" at 1.732,-41.298 h1.52
  text "VDD" at -44.851,-42.517 h2
  text "GND" at -44.902,-45.006 h2
  text "M" at -34.37,-46.81 h12
  text "GND" at -44.851,-47.597 h2
  text "CURIOSITY NANO TOUCH ADAPTER" at -39.822,-49.172 h2.18
Bottom Overlay:
  text "VBUS" at -16.332,40.337 h1.52
  text "NC" at -48.332,40.286 h1.52
  text "VOFF" at -16.332,37.797 h1.52
  text "ID" at -48.387,37.77 h1.52
  text "NC" at -18.237,35.23 h1.52
  text "NC" at -48.332,35.206 h1.52
  text "NC" at -18.237,32.69 h1.52
  text "NC" at -48.332,32.666 h1.52
  text "NC" at -48.332,30.126 h1.52
  text "GND" at -17.12,30.124 h1.52
  text "VCC" at -17.145,27.61 h1.52
  text "NC" at -48.332,27.586 h1.52
  text "XY14" at -48.336,25.095 h1.52
  text "XY3" at -17.704,25.07 h1.52
  text "XY13" at -48.336,22.53 h1.52
  text "XY7" at -17.882,22.53 h1.52
  text "XY11" at -16.993,19.99 h1.52
  text "SDA" at -48.311,19.964 h1.52
  text "GND" at -1.829,19.837 h1.52
  text "ID" at -7.671,19.761 h1.78
  text "SCL" at -48.336,17.45 h1.52
  text "XY8" at -17.704,17.45 h1.52
  text "XY1" at -7.417,17.323 h1.52
  text "XY3" at -1.854,17.272 h1.52
  text "XY1" at -48.336,14.935 h1.52
  text "XY4" at -17.678,14.935 h1.52
  text "XY5" at -7.518,14.808 h1.52
  text "XY7" at -1.905,14.732 h1.52
  text "XY2" at -17.628,12.395 h1.52
  text "XY5" at -48.285,12.37 h1.52
  text "XY2" at -7.493,12.217 h1.52
  text "XY4" at -1.905,12.217 h1.52
  text "XY12" at -16.891,9.83 h1.52
  text "XY6" at -48.285,9.804 h1.52
  text "XY6" at -7.468,9.677 h1.52
  text "XY8" at -1.854,9.677 h1.52
  text "XY10" at -16.332,7.317 h1.52
  text "XY9" at -48.311,7.264 h1.52
  text "SDA" at -7.702,7.149 h1.52
  text "SCL" at -1.914,7.149 h1.52
  text "GND" at -17.12,4.775 h1.52
  text "GND" at -48.235,4.75 h1.52
  text "XY13" at -7.468,4.623 h1.52
  text "XY14" at -1.88,4.623 h1.52
  text "XY17" at -16.891,2.21 h1.52
  text "XY15" at -48.332,2.186 h1.52
  text "XY9" at -7.518,2.083 h1.52
  text "XY10" at -1.829,2.057 h1.52
  text "XY21" at -16.967,-0.33 h1.52
  text "XY19" at -48.332,-0.354 h1.52
  text "XY11" at -7.518,-0.406 h1.52
  text "XY12" at -1.829,-0.457 h1.52
  text "XY18" at -16.891,-2.87 h1.52
  text "XY16" at -48.332,-2.894 h1.52
  text "GND" at -7.544,-3.124 h1.52
  text "VDD" at -2.108,-3.122 h1.52
  text "XY20" at -48.336,-5.41 h1.52
  text "XY22" at -16.942,-5.41 h1.52
  text "XY23" at -48.336,-7.95 h1.52
  text "XY24" at -16.942,-7.95 h1.52
  text "XY26" at -16.916,-10.465 h1.52
  text "XY25" at -48.26,-10.516 h1.52
  text "XY28" at -16.967,-13.03 h1.52
  text "XY27" at -48.332,-13.054 h1.52
  text "NC" at -18.237,-15.545 h1.52
  text "NC" at -48.332,-15.594 h1.52
  text "NC" at -7.645,-15.672 h1.52
  text "GND" at -1.854,-15.723 h1.52
  text "GND" at -17.145,-18.085 h1.52
  text "GND" at -48.209,-18.11 h1.52
  text "XY15" at -7.729,-18.263 h1.52
  text "XY17" at -2.095,-18.263 h1.52
  text "NC" at -18.186,-20.625 h1.52
  text "NC" at -48.332,-20.674 h1.52
  text "XY19" at -7.711,-20.803 h1.52
  text "XY21" at -1.892,-20.803 h1.52
  text "NC" at -18.237,-23.19 h1.52
  text "NC" at -48.332,-23.214 h1.52
  text "XY16" at -7.73,-23.343 h1.52
  text "XY18" at -2.07,-23.343 h1.52
  text "NC" at -18.212,-25.73 h1.52
  text "NC" at -48.332,-25.754 h1.52
  text "XY20" at -7.716,-25.883 h1.52
  text "XY22" at -2.076,-25.883 h1.52
  text "NC" at -18.161,-28.27 h1.52
  text "NC" at -48.332,-28.294 h1.52
  text "SDA" at -7.569,-28.397 h1.52
  text "SCL" at -2.007,-28.448 h1.52
  text "XY27" at -7.746,-30.963 h1.52
  text "XY28" at -2.07,-30.963 h1.52
  text "XY23" at -7.718,-33.503 h1.52
  text "XY24" at -2.103,-33.503 h1.52
  text "XY25" at -7.729,-36.043 h1.52
  text "XY26" at -2.079,-36.043 h1.52
  text "GND" at -7.505,-38.693 h1.52
  text "VDD" at -1.717,-38.693 h1.52
  text "A08-3067 Rev 1" at -15.011,-40.869 h2
  text "c" at -10.465,-50.038 h7.5
  text "p" at -18.694,-50.19 h8
  text "e" at -24.867,-50.495 h8
  text "" at -37.744,-53.518 h12
Mechanical 1:
  the board outline again, w0.254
